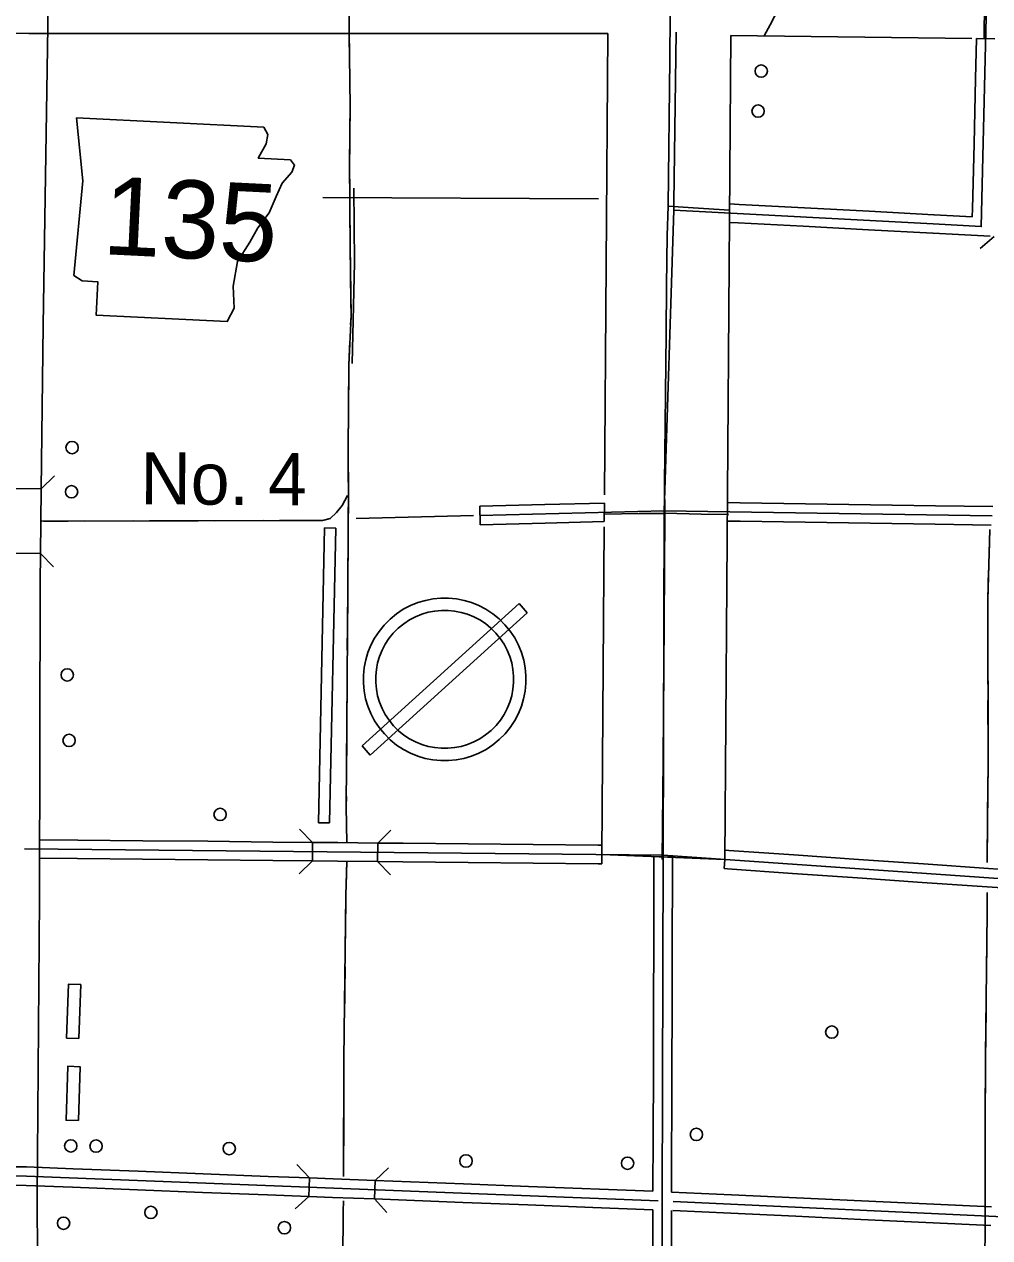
# Model space of a CAD drawing. Extents: x -4306 to 3843, y 131 to 8053.
# Drawn here: x -251 to 1003, y 1865 to 3441 of the extents above; entities that cross this region are included whole.
import ezdxf

# ---------------------------------------------------------------- set-up
doc = ezdxf.new("R2010")
doc.units = 0
for name, color, linetype in [('10', 7, 'Continuous'), ('21', 7, 'Continuous'), ('31', 7, 'Continuous'), ('32', 7, 'Continuous'), ('33', 7, 'Continuous'), ('34', 7, 'Continuous'), ('35', 7, 'Continuous'), ('37', 7, 'Continuous'), ('38', 7, 'Continuous'), ('43', 7, 'Continuous'), ('46', 7, 'Continuous'), ('5', 7, 'Continuous'), ('56', 7, 'Continuous'), ('57', 7, 'Continuous'), ('6', 7, 'Continuous')]:
    doc.layers.add(name, color=color, linetype=linetype)

msp = doc.modelspace()

# ---------------------------------------------------------------- linework, layer by layer
at = {"layer": '10'}
for p, q in [((-220.3, 3437.9), (-220.6, 3615.3)), ((-226.6, 3049.5), (-220.3, 3437.9)), ((-229, 2837.7), (-269, 2838.1)), ((-229.9, 2753.2), (-229, 2837.2)), ((-269.9, 2754), (-229.9, 2753.6))]:
    msp.add_line(p, q, dxfattribs=at)
for points in [[(-226.6, 3049.5), (-229, 2837.2)], [(-229.9, 2753.2), (-230.3, 2716.3), (-231, 2305.2), (-234.2, 1917.5), (-233.4, 1758), (-238.7, 1599), (-240.3, 1434.8), (-238.9, 1200.9), (-242.2, 1053.5), (-244.1, 861.8), (-243.5, 732.4), (-254.4, 657.4), (-262.5, 621.4), (-265.5, 597.6), (-272.4, 440.2), (-274.5, 304.9), (-274.4, 293.9)]]:
    msp.add_lwpolyline(points, dxfattribs=at)
at = {"layer": '21'}
msp.add_lwpolyline([(-183.1, 3319.2), (-174.9, 3237.4), (-186.4, 3114.7), (-175.9, 3107.4), (-155.6, 3106.4), (-157.7, 3063.1), (12.6, 3054.8), (21.6, 3072), (20.3, 3100.5), (25.9, 3132.8), (42.1, 3157.7), (52.5, 3176.2), (67, 3195.8), (76.1, 3217), (83.8, 3234.3), (96.6, 3248.6), (99.8, 3257.9), (94.7, 3264.9), (52.8, 3267), (63.2, 3285.4), (65.2, 3297.5), (60, 3307.1)], close=True, dxfattribs=at)
at = {"layer": '31'}
for p, q in [((566.1, 2166.4), (566.3, 2250.9)), ((566.3, 2250.9), (566.3, 2250.9)), ((590.1, 2166.3), (590.3, 2250.8)), ((565.9, 2081.9), (566.1, 2166.4)), ((589.9, 2081.9), (590.1, 2166.3)), ((-247.9, 1956.9), (-272.1, 1957.2)), ((-187.4, 1954.6), (-247.9, 1956.9)), ((-102.9, 1951.3), (-187.4, 1954.6)), ((65.9, 1944.7), (65.9, 1944.7)), ((119.3, 1942.7), (65.9, 1944.7)), ((118.4, 1918.7), (119.3, 1942.7)), ((150.3, 1941.5), (119.3, 1942.7)), ((204.6, 1939.4), (150.3, 1941.5)), ((203.6, 1915.4), (204.5, 1939.4)), ((204.5, 1939.4), (319.2, 1934.9)), ((-248.5, 1932.9), (-272.4, 1933.2)), ((-188.3, 1930.6), (-248.5, 1932.9)), ((-103.9, 1927.3), (-188.3, 1930.6)), ((319.2, 1934.9), (403.6, 1931.7)), ((565.4, 1925.4), (403.6, 1931.7)), ((118.6, 1918.7), (65, 1920.8)), ((149.4, 1917.5), (118.4, 1918.7)), ((203.6, 1915.4), (149.4, 1917.5)), ((318.3, 1910.9), (203.6, 1915.4)), ((402.7, 1907.7), (318.3, 1910.9)), ((487.1, 1904.4), (402.7, 1907.7)), ((565.4, 1901.4), (487.1, 1904.4))]:
    msp.add_line(p, q, dxfattribs=at)
for points in [[(579.9, 2808.9), (592.5, 3199.4), (592.3, 3209.3), (595.4, 3430.4)], [(577.4, 1912.9), (578.6, 2361.9), (579.9, 2808.9)], [(566.6, 2335.4), (566.6, 2360)], [(566.6, 2360), (590.6, 2359), (590.6, 2335.3)], [(566.3, 2250.9), (566.6, 2335.4)], [(590.6, 2335.3), (590.3, 2250.8)], [(565.6, 1997.4), (565.9, 2081.9)], [(589.9, 2081.9), (589.4, 1924.4)], [(565.4, 1925.4), (565.6, 1997.4)], [(-18.5, 1948), (-102.9, 1951.3)], [(65.9, 1944.7), (-18.5, 1948)], [(-103.9, 1927.3), (-19.4, 1924)], [(-19.4, 1924), (65, 1920.8)]]:
    msp.add_lwpolyline(points, dxfattribs=at)
at = {"layer": '32'}
for p, q in [((984.2, 3370), (985.4, 3422.3)), ((1009.4, 3421.7), (985.4, 3422.3)), ((982.2, 3285.5), (984.2, 3370)), ((980.2, 3201.1), (982.2, 3285.5)), ((665, 3207.6), (677.5, 3206.9)), ((677.5, 3206.9), (761.9, 3202.4)), ((761.9, 3202.4), (846.2, 3197.9)), ((979.9, 3190.7), (980.2, 3201.1)), ((664.8, 3183.5), (676.2, 3182.9)), ((676.2, 3182.9), (760.6, 3178.4)), ((846.2, 3197.9), (929.9, 3193.4)), ((929.9, 3193.4), (930.6, 3193.3)), ((930.6, 3193.3), (979.9, 3190.7)), ((760.6, 3178.4), (845, 3173.9)), ((845, 3173.9), (928.6, 3169.4)), ((928.6, 3169.4), (929.3, 3169.4)), ((929.3, 3169.4), (1003.3, 3165.4)), ((340.7, 2802.9), (579.9, 2808.9)), ((579.9, 2808.9), (1005.6, 2802.5)), ((662.1, 2819.7), (678.8, 2819.4)), ((678.8, 2819.4), (763.3, 2818.2)), ((763.3, 2818.2), (847.7, 2816.9)), ((847.7, 2816.9), (932.2, 2815.6)), ((932.2, 2815.6), (1006.8, 2814.5)), ((662, 2795.7), (678.4, 2795.4)), ((678.4, 2795.4), (762.9, 2794.2)), ((762.9, 2794.2), (847.4, 2792.9)), ((847.4, 2792.9), (931.9, 2791.6)), ((931.9, 2791.6), (1004.4, 2790.5)), ((-181.5, 2381.5), (-230.8, 2381.9)), ((-97, 2380.6), (-181.5, 2381.5)), ((-12.5, 2379.8), (-97, 2380.6)), ((71.9, 2378.9), (-12.5, 2379.8)), ((578.6, 2361.9), (-250.7, 2370.1)), ((123.4, 2378.4), (71.9, 2378.9)), ((123.4, 2378.4), (123.2, 2354.4)), ((156.4, 2378.1), (123.4, 2378.4)), ((208.1, 2377.6), (156.4, 2378.1)), ((208.1, 2377.6), (207.9, 2353.6)), ((240.9, 2377.3), (208.1, 2377.6)), ((325.4, 2376.4), (240.9, 2377.3)), ((409.9, 2375.6), (325.4, 2376.4)), ((494.4, 2374.7), (409.9, 2375.6)), ((499, 2374.7), (494.4, 2374.7)), ((499, 2374.7), (498.9, 2362.7)), ((658.8, 2368.4), (658.7, 2356.3)), ((663.8, 2368), (658.8, 2368.4)), ((748.1, 2362.1), (663.8, 2368)), ((-181.8, 2357.5), (-230.9, 2357.9)), ((-97.3, 2356.6), (-181.8, 2357.5)), ((-12.8, 2355.8), (-97.3, 2356.6)), ((71.7, 2354.9), (-12.8, 2355.8)), ((123.2, 2354.4), (71.7, 2354.9)), ((156.2, 2354.1), (123.2, 2354.4)), ((207.9, 2353.6), (156.2, 2354.1)), ((240.7, 2353.3), (207.9, 2353.6)), ((325.2, 2352.4), (240.7, 2353.3)), ((409.6, 2351.6), (325.2, 2352.4)), ((494.1, 2350.7), (409.6, 2351.6)), ((498.8, 2350.7), (494.1, 2350.7)), ((498.9, 2362.7), (498.8, 2350.7)), ((1421.6, 2303.3), (578.6, 2361.9)), ((658.7, 2356.3), (657.9, 2344.4)), ((832.4, 2356.3), (748.1, 2362.1)), ((916.7, 2350.4), (832.4, 2356.3)), ((1001, 2344.6), (916.7, 2350.4)), ((662.2, 2344.1), (657.9, 2344.4)), ((746.5, 2338.2), (662.2, 2344.1)), ((830.8, 2332.3), (746.5, 2338.2)), ((915, 2326.5), (830.8, 2332.3)), ((1085.3, 2338.7), (1001, 2344.6)), ((999.3, 2320.6), (915, 2326.5)), ((1083.6, 2314.8), (999.3, 2320.6)), ((-248.2, 1944.9), (-1090.3, 1954.4)), ((572, 1913.1), (-248.2, 1944.9)), ((667.4, 1920.7), (589.4, 1924.4)), ((577.4, 1912.9), (577.5, 1509.2)), ((1417.7, 1873.9), (591.7, 1912.3)), ((751.8, 1916.8), (667.4, 1920.7)), ((836.2, 1912.9), (751.8, 1916.8)), ((920.6, 1909), (836.2, 1912.9)), ((1005, 1905.1), (920.6, 1909)), ((565.4, 1901.4), (565.4, 1828.4)), ((589.4, 1900.3), (589.4, 1828.4)), ((666.3, 1896.8), (591.1, 1900.3)), ((750.7, 1892.9), (666.3, 1896.8)), ((835.1, 1888.9), (750.7, 1892.9)), ((919.5, 1885), (835.1, 1888.9)), ((1003.9, 1881.1), (919.5, 1885))]:
    msp.add_line(p, q, dxfattribs=at)
for points in [[(929.3, 3181.4), (991.6, 3178), (1001, 3577.3)], [(592.5, 3199.4), (929.3, 3181.4)]]:
    msp.add_lwpolyline(points, dxfattribs=at)
at = {"layer": '33'}
for p, q in [((734.6, 3472.7), (717.4, 3439.8)), ((995.7, 3469.1), (995.3, 3422.6)), ((587.5, 3452.1), (587.2, 3395.7)), ((717.4, 3439.8), (709.6, 3425.7)), ((587.2, 3395.7), (585.1, 3204.7)), ((585.2, 3204.7), (583.6, 3166.6)), ((617.6, 3202.5), (585.1, 3204.7)), ((664.9, 3199.2), (617.6, 3202.5)), ((583.6, 3166.6), (582.8, 3101.1)), ((582.8, 3101.1), (582.4, 3039.2)), ((582.4, 3039.2), (580.3, 2843.7)), ((580.3, 2843.7), (580.7, 2804)), ((580.7, 2806.1), (627.8, 2804.5)), ((580.7, 2804), (579.8, 2663.9)), ((627.8, 2804.5), (663.4, 2804.3)), ((579.8, 2663.9), (578.5, 2485.6)), ((578.5, 2485.6), (577.4, 2356.1))]:
    msp.add_line(p, q, dxfattribs=at)
at = {"layer": '34'}
for p, q in [((547.4, 2805.6), (502.1, 2804.7)), ((580.6, 2805.3), (547.4, 2805.6))]:
    msp.add_line(p, q, dxfattribs=at)
at = {"layer": '35'}
for points in [[(176.8, 3227.8), (177.7, 3131)], [(177.7, 3131), (174.8, 3000.3)], [(168.6, 2828.8), (161.9, 2815.8), (154.6, 2806.7), (146.3, 2799), (136.1, 2796.4), (-228.2, 2795.5)]]:
    msp.add_lwpolyline(points, dxfattribs=at)
at = {"layer": '37'}
for p, q in [((-249, 2837.9), (-249, 2837.9)), ((-249.9, 2753.8), (-249.9, 2753.8))]:
    msp.add_line(p, q, dxfattribs=at)
for points in [[(-229, 2837.7), (-211.8, 2854.5)], [(-213.1, 2736.4), (-229.9, 2753.6)]]:
    msp.add_lwpolyline(points, dxfattribs=at)
at = {"layer": '38'}
msp.add_line((1008.4, 3165.1), (990.2, 3149.4), dxfattribs=at)
for points in [[(106.6, 2395.6), (123.4, 2378.4)], [(208.1, 2377.6), (225.2, 2394.4)], [(123.2, 2354.4), (106.1, 2337.6)], [(224.7, 2336.4), (207.9, 2353.6)], [(103, 1960.3), (119.3, 1942.7)], [(204.5, 1939.4), (222.1, 1955.7)], [(118.4, 1918.7), (100.8, 1902.4)], [(219.9, 1897.8), (203.6, 1915.4)]]:
    msp.add_lwpolyline(points, dxfattribs=at)
at = {"layer": '43'}
for points in [[(171.8, 3589.1), (171.4, 3563.3), (171.3, 3496.1), (171, 3432.6), (172.2, 3333.7), (171.4, 3260.5), (172.2, 3153.3), (173.3, 3061.5), (170.6, 2998.5), (169.4, 2887.7), (169.9, 2831.1), (169.7, 2779.7), (168.3, 2589.1), (167.2, 2425), (167.8, 2378)], [(171.1, 3451.8), (171, 3432.6), (171.5, 3388.4)], [(171.8, 3367.3), (172.2, 3333.7), (171.9, 3303.9)], [(171.6, 3282.8), (171.4, 3260.5), (171.7, 3219.4)], [(171.9, 3198.3), (172.2, 3153.3), (172.4, 3134.9)], [(172.7, 3113.8), (173, 3082.1)], [(173, 3082.1), (173.3, 3061.5), (172.8, 3050.5)], [(171.9, 3029.4), (170.6, 2998.5), (170.3, 2966)], [(170, 2944.9), (169.4, 2887.7), (169.5, 2881.5)], [(169.6, 2860.4), (169.9, 2831.1), (169.8, 2797.1)], [(-225.8, 2795.5), (136.1, 2796.4), (146.3, 2799), (154.6, 2806.7), (161.9, 2815.8), (168.6, 2828.8)], [(-225.8, 2795.5), (-194.1, 2795.5)], [(-173, 2795.6), (-109.6, 2795.8)], [(-88.5, 2795.8), (-25.1, 2796)], [(-4, 2796), (59.4, 2796.2)], [(80.5, 2796.3), (136.1, 2796.4), (143.6, 2798.3)], [(169.7, 2775.9), (169.2, 2712.6)], [(1002.6, 2784.5), (1000.2, 2693.2), (1000.5, 2483.8), (999.4, 2362.3), (999.4, 2352.5)], [(1002.6, 2784.5), (1001.7, 2752.8)], [(1001.2, 2731.7), (1000.2, 2693.2), (1000.2, 2668.3)], [(169, 2691.4), (168.5, 2628.1)], [(1000.2, 2647.2), (1000.3, 2583.9)], [(168.4, 2607), (168.3, 2589.1), (168.2, 2575.3)], [(168.2, 2575.3), (168, 2543.6)], [(1000.3, 2562.7), (1000.4, 2499.4)], [(167.8, 2522.5), (167.4, 2459.1)], [(1000.4, 2478.2), (999.9, 2414.9)], [(167.3, 2438), (167.2, 2425), (167.8, 2378)], [(999.7, 2393.8), (999.4, 2362.3), (999.4, 2352.5)], [(167.7, 2354), (166.6, 2309.5), (164.1, 2097.3), (163.7, 1945.2), (163.7, 1944.6)], [(167.7, 2354), (166.9, 2322.3)], [(166.5, 2301.2), (165.8, 2237.8)], [(999.3, 2313.2), (999.2, 2286.4), (997.2, 2101.7), (996.6, 2003.3), (996.9, 1879.7), (995.5, 1749.8), (995.1, 1656.3), (994.6, 1501.8), (994.6, 1500.8)], [(999.3, 2313.2), (999.2, 2286.4), (999.2, 2281.5)], [(999, 2260.4), (998.3, 2197)], [(165.5, 2216.7), (164.8, 2153.3)], [(998, 2175.9), (997.4, 2112.5)], [(164.5, 2132.2), (164.1, 2097.3), (164, 2068.9)], [(997.2, 2091.4), (996.8, 2028.1)], [(164, 2047.7), (163.8, 1984.4)], [(996.7, 2006.9), (996.6, 2003.3), (996.8, 1943.6)], [(163.7, 1963.2), (163.7, 1945.2), (163.7, 1944.6)], [(163.4, 1912.9), (163.3, 1899.3), (162.2, 1772.3), (161.1, 1685.1), (157.9, 1537.8)], [(163.4, 1912.9), (163.3, 1899.3), (163.1, 1881.2)]]:
    msp.add_lwpolyline(points, dxfattribs=at)
at = {"layer": '46'}
for p, q in [((340.4, 2814.9), (424.9, 2817.1)), ((341, 2790.9), (340.4, 2814.9)), ((424.9, 2817.1), (502.3, 2819)), ((502.1, 2795), (502.3, 2819)), ((341, 2790.9), (425.5, 2793.1)), ((425.5, 2793.1), (502.1, 2795))]:
    msp.add_line(p, q, dxfattribs=at)
at = {"layer": '5'}
for p, q in [((136.6, 3215.9), (494.7, 3214.1)), ((179.8, 2798.8), (332.3, 2802.8))]:
    msp.add_line(p, q, dxfattribs=at)
at = {"layer": '56'}
for points in [[(-180, 2123.8), (-196, 2124.4), (-193.7, 2194.3), (-177.7, 2193.8)], [(-180.7, 2017.2), (-196.7, 2017.7), (-194.4, 2087.7), (-178.4, 2087.1)]]:
    msp.add_lwpolyline(points, close=True, dxfattribs=at)
for centre in [(705.9, 3380), (701.8, 3328), (-188.9, 2891), (-189.5, 2833.7), (-195.1, 2595.8), (-192.8, 2510.8), (3.3, 2414.7), (797.5, 2132), (621.7, 1999.2), (-190.6, 1984.2), (-157.8, 1984), (15.1, 1980.9), (322.6, 1964.7), (532.4, 1961.7), (-200, 1883.9), (-86.5, 1897.9), (86.8, 1878.1)]:
    msp.add_circle(centre, 8, dxfattribs=at)
at = {"layer": '57'}
for p, q in [((138.9, 2786.9), (130.9, 2404)), ((138.9, 2786.9), (153.4, 2786.6)), ((153.4, 2786.6), (145.4, 2403.7)), ((391.5, 2688.4), (187.6, 2503.6)), ((402.2, 2676.6), (391.5, 2688.4)), ((198.3, 2491.7), (402.2, 2676.6)), ((187.6, 2503.6), (198.3, 2491.7)), ((145.4, 2403.7), (130.9, 2404))]:
    msp.add_line(p, q, dxfattribs=at)
for radius, start, end in [(105.6, 42.2006, 222.2006), (89.6, 42.2006, 222.2006), (105.6, 222.2006, 42.2006), (89.6, 222.2006, 42.2006)]:
    msp.add_arc((294.9, 2590.1), radius, start, end, dxfattribs=at)
at = {"layer": '6'}
msp.add_line((658.7, 2356.3), (498.9, 2362.7), dxfattribs=at)
for points in [[(506.8, 3428.7), (-245, 3428.6), (-1084.8, 3430.5)], [(506.8, 3428.7), (502.3, 2829.6)], [(658.7, 2356.3), (666.6, 3426.2)], [(666.6, 3426.2), (979.2, 3422.4)], [(502, 2788), (498.9, 2362.7)]]:
    msp.add_lwpolyline(points, dxfattribs=at)

# ---------------------------------------------------------------- texts
at = {"layer": '21'}
msp.add_text('135', height=101.29, rotation=357.2006, dxfattribs=at).set_placement((-150.2, 3142.3))
at = {"layer": '43'}
msp.add_text('No. 4', height=67.59, rotation=359.6372, dxfattribs=at).set_placement((-100.2, 2817.5))

doc.saveas('drawing.dxf')
